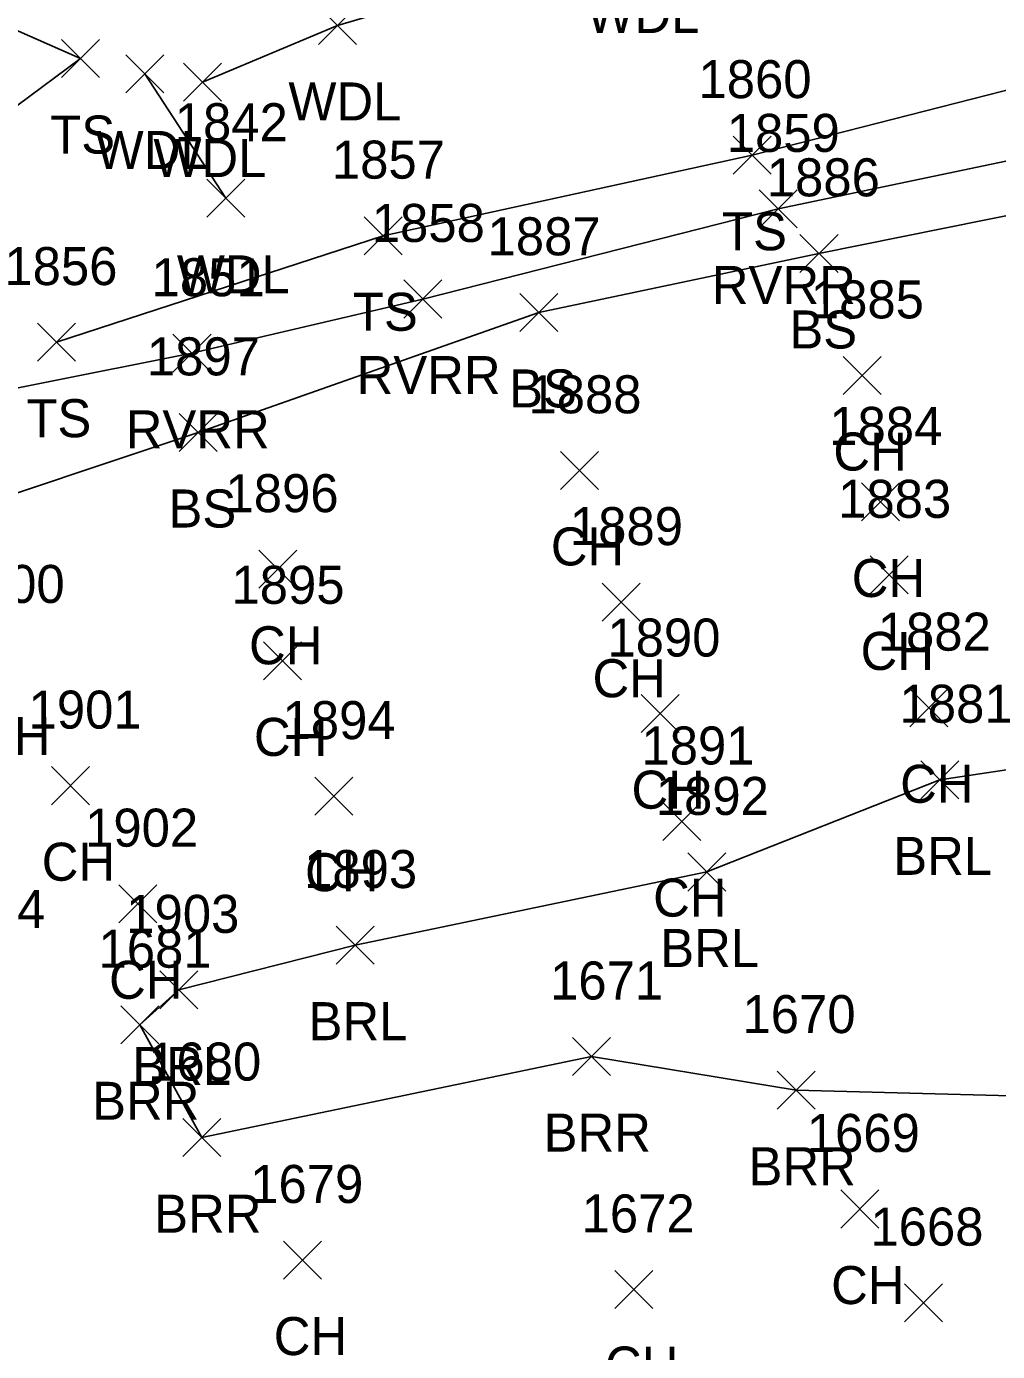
# Model space of a CAD drawing. Extents: x 1616726 to 1619875, y 273782 to 276557.
# Drawn here: x 1617043.8 to 1617094.9, y 276265.9 to 276335.6 of the extents above; entities that cross this region are included whole.
import ezdxf

# ---------------------------------------------------------------- set-up
doc = ezdxf.new("R2010")
doc.units = 0
for name, color, linetype in [('L_A', 7, 'Continuous'), ('L_I', 7, 'Continuous'), ('L_TIC', 7, 'Continuous'), ('LABL', 7, 'Continuous'), ('LAWA', 7, 'Continuous'), ('LAWE', 7, 'Continuous'), ('LELB', 7, 'Continuous')]:
    doc.layers.add(name, color=color, linetype=linetype)

msp = doc.modelspace()

# ---------------------------------------------------------------- linework, layer by layer
at = {"layer": 'L_TIC'}
for points in [[(1617059.163, 276334.633), (1617061.163, 276336.633)], [(1617061.163, 276334.633), (1617059.163, 276336.633)], [(1617045.634, 276332.892), (1617047.634, 276334.892)], [(1617047.634, 276332.892), (1617045.634, 276334.892)], [(1617049.021, 276332.081), (1617051.021, 276334.081)], [(1617051.021, 276332.081), (1617049.021, 276334.081)], [(1617052.06, 276331.653), (1617054.06, 276333.653)], [(1617054.06, 276331.653), (1617052.06, 276333.653)], [(1617080.983, 276327.807), (1617082.983, 276329.807)], [(1617082.983, 276327.807), (1617080.983, 276329.807)], [(1617053.291, 276325.541), (1617055.291, 276327.541)], [(1617055.291, 276325.541), (1617053.291, 276327.541)], [(1617082.344, 276324.98), (1617084.344, 276326.98)], [(1617084.344, 276324.98), (1617082.344, 276326.98)], [(1617061.559, 276323.574), (1617063.559, 276325.574)], [(1617063.559, 276323.574), (1617061.559, 276325.574)], [(1617084.495, 276322.643), (1617086.495, 276324.643)], [(1617086.495, 276322.643), (1617084.495, 276324.643)], [(1617063.656, 276320.245), (1617065.656, 276322.245)], [(1617065.656, 276320.245), (1617063.656, 276322.245)], [(1617069.749, 276319.542), (1617071.749, 276321.542)], [(1617071.749, 276319.542), (1617069.749, 276321.542)], [(1617044.381, 276317.976), (1617046.381, 276319.976)], [(1617046.381, 276317.976), (1617044.381, 276319.976)], [(1617051.505, 276317.389), (1617053.505, 276319.389)], [(1617053.505, 276317.389), (1617051.505, 276319.389)], [(1617086.761, 276316.224), (1617088.761, 276318.224)], [(1617088.761, 276316.224), (1617086.761, 276318.224)], [(1617051.825, 276313.228), (1617053.825, 276315.228)], [(1617053.825, 276313.228), (1617051.825, 276315.228)], [(1617071.898, 276311.233), (1617073.898, 276313.233)], [(1617073.898, 276311.233), (1617071.898, 276313.233)], [(1617087.729, 276309.572), (1617089.729, 276311.572)], [(1617089.729, 276309.572), (1617087.729, 276311.572)], [(1617056.017, 276306.033), (1617058.017, 276308.033)], [(1617058.017, 276306.033), (1617056.017, 276308.033)], [(1617088.195, 276305.737), (1617090.195, 276307.737)], [(1617090.195, 276305.737), (1617088.195, 276307.737)], [(1617074.09, 276304.301), (1617076.09, 276306.301)], [(1617076.09, 276304.301), (1617074.09, 276306.301)], [(1617056.274, 276301.215), (1617058.274, 276303.215)], [(1617058.274, 276301.215), (1617056.274, 276303.215)], [(1617076.141, 276298.441), (1617078.141, 276300.441)], [(1617078.141, 276298.441), (1617076.141, 276300.441)], [(1617090.278, 276298.751), (1617092.278, 276300.751)], [(1617092.278, 276298.751), (1617090.278, 276300.751)], [(1617090.86, 276294.96), (1617092.86, 276296.96)], [(1617092.86, 276294.96), (1617090.86, 276296.96)], [(1617045.11, 276294.652), (1617047.11, 276296.652)], [(1617047.11, 276294.652), (1617045.11, 276296.652)], [(1617058.962, 276294.098), (1617060.962, 276296.098)], [(1617060.962, 276294.098), (1617058.962, 276296.098)], [(1617077.279, 276292.764), (1617079.279, 276294.764)], [(1617079.279, 276292.764), (1617077.279, 276294.764)], [(1617078.601, 276290.112), (1617080.601, 276292.112)], [(1617080.601, 276290.112), (1617078.601, 276292.112)], [(1617048.653, 276288.444), (1617050.653, 276290.444)], [(1617050.653, 276288.444), (1617048.653, 276290.444)], [(1617060.096, 276286.266), (1617062.096, 276288.266)], [(1617062.096, 276286.266), (1617060.096, 276288.266)], [(1617050.819, 276283.909), (1617052.819, 276285.909)], [(1617052.819, 276283.909), (1617050.819, 276285.909)], [(1617048.761, 276282.078), (1617050.761, 276284.078)], [(1617050.761, 276282.078), (1617048.761, 276284.078)], [(1617072.518, 276280.406), (1617074.518, 276282.406)], [(1617074.518, 276280.406), (1617072.518, 276282.406)], [(1617083.298, 276278.638), (1617085.298, 276280.638)], [(1617085.298, 276278.638), (1617083.298, 276280.638)], [(1617052.026, 276276.141), (1617054.026, 276278.141)], [(1617054.026, 276276.141), (1617052.026, 276278.141)], [(1617086.646, 276272.388), (1617088.646, 276274.388)], [(1617088.646, 276272.388), (1617086.646, 276274.388)], [(1617057.317, 276269.705), (1617059.317, 276271.705)], [(1617059.317, 276269.705), (1617057.317, 276271.705)], [(1617074.745, 276268.155), (1617076.745, 276270.155)], [(1617076.745, 276268.155), (1617074.745, 276270.155)], [(1617089.987, 276267.461), (1617091.987, 276269.461)], [(1617091.987, 276267.461), (1617089.987, 276269.461)]]:
    msp.add_lwpolyline(points, dxfattribs=at)
at = {"layer": 'LABL'}
for points in [[(1617133.092, 276304.647), (1617114.885, 276299.412), (1617091.86, 276295.96), (1617079.601, 276291.112), (1617061.096, 276287.266), (1617051.819, 276284.909)], [(1617049.761, 276283.078), (1617051.819, 276284.909)], [(1617112.629, 276284.466), (1617102.261, 276279.162), (1617084.298, 276279.638), (1617073.518, 276281.406), (1617053.026, 276277.141), (1617049.761, 276283.078)]]:
    msp.add_lwpolyline(points, dxfattribs=at)
at = {"layer": 'LAWA'}
for points in [[(1617131.584, 276346.038), (1617114.336, 276341.96), (1617075.845, 276340.233), (1617060.163, 276335.633), (1617053.06, 276332.653)], [(1617050.021, 276333.081), (1617054.291, 276326.541)]]:
    msp.add_lwpolyline(points, dxfattribs=at)
at = {"layer": 'LAWE'}
msp.add_lwpolyline([(1616789.066, 276346.617), (1616813.729, 276340.234), (1616836.199, 276333.67), (1616856.332, 276327.47), (1616874.716, 276318.98), (1616895.397, 276309.259), (1616910.771, 276301.56), (1616920.919, 276300.828), (1616931.346, 276302.765), (1616941.571, 276299.741), (1616947.812, 276295.799), (1616953.389, 276297.474), (1616960.888, 276300.059), (1616975.487, 276304.634), (1616989.935, 276306.407), (1617005.692, 276306.569), (1617020.087, 276309.056), (1617036.575, 276315.223), (1617052.505, 276318.389), (1617064.656, 276321.245), (1617083.344, 276325.98), (1617106.129, 276330.762), (1617129.705, 276333.809)], dxfattribs=at)
at = {"layer": 'LELB'}
for points in [[(1616978.199, 276327.348), (1616991.321, 276323.975), (1617002.989, 276326.908), (1617009.955, 276326.56), (1617017.916, 276322.159), (1617029.869, 276324.32), (1617039.92, 276328.912), (1617046.634, 276333.892), (1617037.877, 276337.76), (1617028.239, 276334.405), (1617014.137, 276333.953), (1617001.116, 276333.136)], [(1617045.381, 276318.976), (1617062.559, 276324.574), (1617081.983, 276328.807), (1617104.241, 276334.482), (1617128.568, 276335.527)], [(1617129.884, 276332.128), (1617121.079, 276329.53), (1617107.418, 276328.047), (1617085.495, 276323.643), (1617070.749, 276320.542), (1617052.825, 276314.228), (1617038.577, 276309.473), (1617032.524, 276309.943), (1617021.414, 276306.236), (1617009.943, 276306.043), (1616997.429, 276304.853), (1616977.398, 276301.812), (1616963.959, 276298.067)]]:
    msp.add_lwpolyline(points, dxfattribs=at)

# ---------------------------------------------------------------- texts
at = {"layer": 'L_A'}
for s, p in [('WDL', (1617073.262, 276335.233)), ('WDL', (1617057.58, 276330.633)), ('TS', (1617045.044, 276328.892)), ('WDL', (1617047.438, 276328.081)), ('WDL', (1617050.477, 276327.653)), ('TS', (1617080.392, 276323.807)), ('WDL', (1617051.709, 276321.541)), ('RVRR', (1617079.856, 276320.98)), ('TS', (1617060.968, 276319.574)), ('BS', (1617083.936, 276318.643)), ('RVRR', (1617061.167, 276316.245)), ('BS', (1617069.19, 276315.542)), ('TS', (1617043.791, 276313.976)), ('RVRR', (1617049.016, 276313.389)), ('CH', (1617086.249, 276312.224)), ('BS', (1617051.266, 276309.228)), ('CH', (1617071.386, 276307.233)), ('CH', (1617087.217, 276305.572)), ('CH', (1617055.505, 276302.033)), ('CH', (1617087.683, 276301.737)), ('CH', (1617073.578, 276300.301)), ('CH', (1617041.203, 276297.261)), ('CH', (1617055.762, 276297.215)), ('CH', (1617089.766, 276294.751)), ('CH', (1617075.629, 276294.441)), ('CH', (1617044.599, 276290.652)), ('BRL', (1617089.403, 276290.96)), ('CH', (1617058.451, 276290.098)), ('CH', (1617076.767, 276288.764)), ('BRL', (1617077.144, 276286.112)), ('CH', (1617048.141, 276284.444)), ('BRL', (1617058.639, 276282.266)), ('BRL', (1617049.362, 276279.909)), ('BRR', (1617047.249, 276278.078)), ('BRR', (1617071.006, 276276.406)), ('BRR', (1617081.786, 276274.638)), ('BRR', (1617050.515, 276272.141)), ('CH', (1617086.134, 276268.388)), ('CH', (1617056.805, 276265.705)), ('CH', (1617074.234, 276264.155))]:
    msp.add_text(s, height=2, dxfattribs=at).set_placement(p)
at = {"layer": 'L_I'}
for s, p in [('1860', (1617079.156, 276331.807)), ('1842', (1617051.598, 276329.541)), ('1859', (1617080.643, 276328.98)), ('1857', (1617059.866, 276327.574)), ('1886', (1617082.747, 276326.643)), ('1858', (1617061.963, 276324.245)), ('1887', (1617068.057, 276323.542)), ('1856', (1617042.633, 276321.976)), ('1851', (1617050.379, 276321.389)), ('1885', (1617085.068, 276320.224)), ('1897', (1617050.133, 276317.228)), ('1888', (1617070.205, 276315.233)), ('1884', (1617086.036, 276313.572)), ('1896', (1617054.269, 276310.033)), ('1883', (1617086.502, 276309.737)), ('1889', (1617072.389, 276308.301)), ('1900', (1617039.857, 276305.261)), ('1895', (1617054.581, 276305.215)), ('1890', (1617074.361, 276302.441)), ('1882', (1617088.585, 276302.751)), ('1881', (1617089.734, 276298.96)), ('1901', (1617043.906, 276298.652)), ('1894', (1617057.27, 276298.098)), ('1891', (1617076.153, 276296.764)), ('1892', (1617076.908, 276294.112)), ('1902', (1617046.881, 276292.444)), ('1893', (1617058.403, 276290.266)), ('1904', (1617038.838, 276288.171)), ('1903', (1617049.047, 276287.909)), ('1681', (1617047.588, 276286.078)), ('1671', (1617071.344, 276284.406)), ('1670', (1617081.471, 276282.638)), ('1680', (1617050.2, 276280.141)), ('1669', (1617084.851, 276276.388)), ('1679', (1617055.569, 276273.705)), ('1672', (1617073.005, 276272.155)), ('1668', (1617088.2, 276271.461))]:
    msp.add_text(s, height=2, dxfattribs=at).set_placement(p)

doc.saveas('drawing.dxf')
